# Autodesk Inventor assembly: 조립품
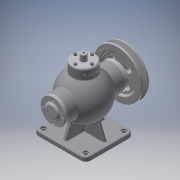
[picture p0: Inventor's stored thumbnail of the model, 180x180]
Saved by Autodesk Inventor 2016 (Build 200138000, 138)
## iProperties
Created: 2017-01
Part Number: 조립품
Material: 일반
Document SubType Name: Assembly
Designer: Administrator
Author: Administrator
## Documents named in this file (19)
- C:\Users\Administrator\Desktop\470130V1007\조립품.iam
- C:\Users\Administrator\Desktop\470130V1007\V-벨트풀리.ipt
- C:\Users\Administrator\Desktop\470130V1007\너트 M8.ipt
- C:\Users\Administrator\Desktop\470130V1007\뒤커버.ipt
- C:\Users\Administrator\Desktop\470130V1007\멈춤링- 15 x 1.ipt
- C:\Users\Administrator\Desktop\470130V1007\멈춤링- 35x1.6.ipt
- KS B 1336 - 35x1.6.ipt
- C:\Users\Administrator\Desktop\470130V1007\베어링- 6202.ipt
- KS B 2023 - 6202 - 15 x 35 x 11 - 7.8.ipt
- C:\Users\Administrator\Desktop\470130V1007\본체.ipt
- C:\Users\Administrator\Desktop\470130V1007\볼트 M4 x 12.ipt
- C:\Users\Administrator\Desktop\470130V1007\볼트 M4 x 16.ipt
- C:\Users\Administrator\Desktop\470130V1007\부시.ipt
- C:\Users\Administrator\Desktop\470130V1007\상부커버.ipt
- C:\Users\Administrator\Desktop\470130V1007\슬라이드.ipt
- C:\Users\Administrator\Desktop\470130V1007\앞커버.ipt
- C:\Users\Administrator\Desktop\470130V1007\오일실 15 30 7.ipt
- C:\Users\Administrator\Desktop\470130V1007\키 4 x 4 x 12.ipt
- C:\Users\Administrator\Desktop\470130V1007\편심축.ipt
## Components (16 placed, 5 different names)
1. V-벨트풀리:1
2. KS B 1336 - 35x1.6:1
3. KS B 2023 - 6202 - 15 x 35 x 11 - 7.8:1
4. KS B 2023 - 6202 - 15 x 35 x 11 - 7.8:2
5. KS B 1021 - 에 따름 ISO 1207 - 미터 A  M 4 x 12:1
6. KS B 1021 - 에 따름 ISO 1207 - 미터 A  M 4 x 12:2
7. KS B 1021 - 에 따름 ISO 1207 - 미터 A  M 4 x 12:3
8. KS B 1021 - 에 따름 ISO 1207 - 미터 A  M 4 x 12:4
9. ISO 4762 M4 x 16:1
10. ISO 4762 M4 x 16:2
11. ISO 4762 M4 x 16:3
12. ISO 4762 M4 x 16:4
13. ISO 4762 M4 x 16:5
14. ISO 4762 M4 x 16:6
15. ISO 4762 M4 x 16:7
16. ISO 4762 M4 x 16:8
